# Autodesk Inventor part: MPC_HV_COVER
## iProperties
Shininess: 64.0
Length Units: 11269
Angle Units: 11279
Time Units: 11290
Mass Units: 11283
Length Display Precision: 3
Angle Display Precision: 2
Compacted: True
Part Number: MPC_HV_COVER
Document SubType Name: Modeling
Created: 2004-08
Material: Lexan, Clear
Designer: John Blackburn
Manufacturer: Standard
Standards Organization: Custom
Density: 0.0
Volumn: 0.0
Area: 0.0
PropertySet Name: Model Information
Control State: 0
Master: False
Checked Out: False
Author: John Blackburn
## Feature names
1. Extrusion1
2. Hole1
